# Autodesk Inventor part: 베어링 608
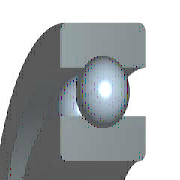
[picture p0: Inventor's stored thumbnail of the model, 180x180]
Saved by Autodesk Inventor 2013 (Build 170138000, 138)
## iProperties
IsCustomPart: 1
Created: 2009-02
Part Number: 베어링 608
Material: 강, 연강
Description: 깊은 그루브 볼 베어링
Document SubType Name: Modeling
Standard: KS B 2023
Designer: 한국산업디자인학원
Standards Organization: KS
Language: ko-KR
Size Designation: 608 - 8 x 22 x 7
Categories: <MemberInstance><Categories><Category DisplayName="샤프트 부품" InternalName="7f7aeb1f-a693-4053-b835-cee3144e0d98" Mnemonic="SHFT"><Category DisplayName="베어링" Inter
Density: 1 g/cm^3
Author: 한국산업디자인학원
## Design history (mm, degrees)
sketch "스케치" dims "d0" = 3.64 (= -0.26 x WD + 0.26 x BD)
  geometry: L1 (1.68, 7.5)-(5.32, 7.5); L2 (3.5, 7.5)-(3.5, 5.68); L3 (3.5, 7.5)-(3.5, 9.32); L4 (2.148, 6.282)-(0, 6.282); L5 (0, 4)-(7, 4); L6 (2.148, 8.718)-(0, 8.718); L7 (0, 11)-(7, 11); L8 (7, 4)-(7, 6.282); L9 (4.852, 6.282)-(7, 6.282); L10 (4.852, 8.718)-(7, 8.718); L11 (7, 11)-(7, 8.718); L12 (-1.4, 0)-(8.4, 0) reference; L13 (0, -0.3)-(0, 5.3) reference
  constraints: 22 end point, 4 point on line, 2 collinear, 2 perpendicular, 2 symmetric about line, 1 midpoint, 1 parallel, 14 other
  dimensions: "d9" = 8 diameter of L5 L12 (= WD); "d11" = 22 diameter of L7 L12 (= BD); "d12" = 7 distance between parallel lines of L8 L13 (= KB); "d13" = 12.564 diameter of L9 L12 (= 0.326 x BD + 0.674 x WD)
revolve "본체" stored, may be unused: angle "d6" = 90 deg
revolve "볼" stored, may be unused: angle "d7" = 90 deg
pattern_circular "IDS_ARRAYBALL[SIMPL:T]" dims angle "d3" = 360 deg
body "Solid1"
fillet "모깎기1" dims "d1" = 0.3 (= KRS)
other parameters: "WD" = 8 [user parameter; used in 5 equation terms], "BD" = 22 [user parameter; used in 5 equation terms], "KB" = 7 [user parameter; used in 1 equation term], "KRS" = 0.3 [user parameter; used in 1 equation term], "d4" = 0, "d5" = 0, "d8" = 0, "d14" = 0, "d15" = 0, "BBA" = 0 [user parameter], "BC0" = 1370000 [user parameter], "BC" = 3250000 [user parameter], "BR" = 11 (= 0.5 x BD) [user parameter], "WR" = 4 (= 0.5 x WD) [user parameter]
